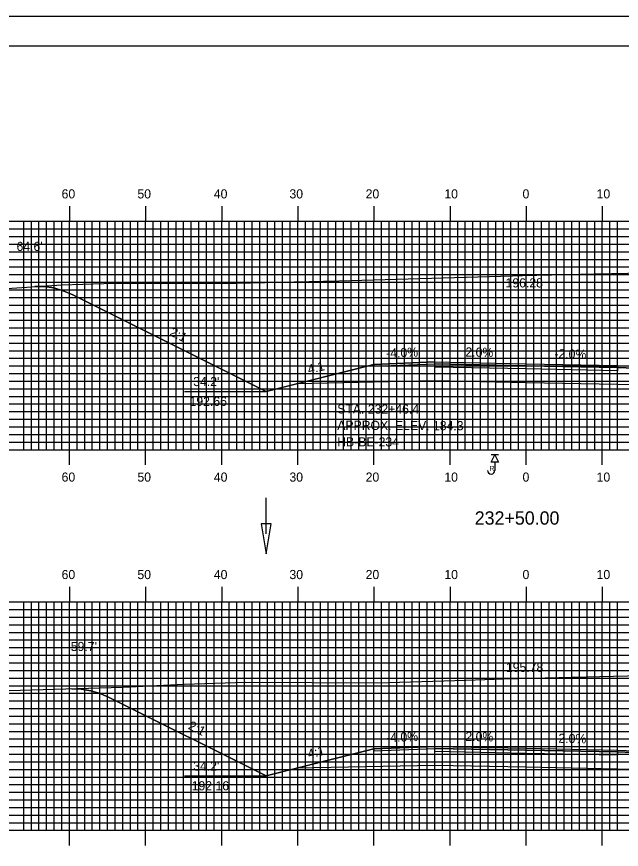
# Model space of a CAD drawing. Extents: x 1799568 to 1799912, y 442591 to 442811.
# Drawn here: x 1799667.1 to 1799746.5, y 442701.2 to 442810.5 of the extents above; entities that cross this region are included whole.
import ezdxf

# ---------------------------------------------------------------- set-up
doc = ezdxf.new("R2010")
doc.units = 0
for name, color, linetype in [('ANNOTATION', 7, 'Continuous'), ('BORDER', 7, 'Continuous'), ('BORING - REFUSAL', 7, 'Continuous'), ('D_Drainage_Ditch_Line', 7, 'Continuous'), ('D_Roadway_Centerline', 7, 'Continuous'), ('D_Roadway_Centerline_Text', 7, 'Continuous'), ('D_Roadway_Edge_Shoulder', 7, 'Continuous'), ('D_Roadway_Edge_TW', 7, 'Continuous'), ('D_Roadway_Pavement', 7, 'Continuous'), ('D_Roadway_SlopeLines', 7, 'Continuous'), ('D_Roadway_SubGrade', 7, 'Continuous'), ('D_Text_Standard', 7, 'Continuous'), ('H_V ANNOTATION', 7, 'Continuous'), ('MAJOR', 7, 'Continuous'), ('MINOR', 7, 'Continuous'), ('PDRAIN', 7, 'Continuous'), ('PLOT BOUNDARY', 7, 'Continuous'), ('S_Roadway_Centerline', 7, 'Continuous')]:
    doc.layers.add(name, color=color, linetype=linetype)

msp = doc.modelspace()

# ---------------------------------------------------------------- linework, layer by layer
at = {"layer": 'BORDER'}
msp.add_lwpolyline([(1799584.41, 442596.67), (1799904.41, 442596.67), (1799904.41, 442806.67), (1799584.41, 442806.67)], close=True, dxfattribs=at)
at = {"layer": 'BORING - REFUSAL'}
for p, q in [((1799730.39, 442752.97), (1799729.43, 442752.97)), ((1799729.91, 442752.01), (1799729.91, 442750.95))]:
    msp.add_line(p, q, dxfattribs=at)
msp.add_lwpolyline([(1799729.91, 442752.97), (1799730.39, 442752.01), (1799729.43, 442752.01)], close=True, dxfattribs=at)
msp.add_arc((1799729.42, 442750.95), 0.485, 180, 0, dxfattribs=at)
at = {"layer": 'D_Drainage_Ditch_Line'}
msp.add_line((1799699.84, 442742.63), (1799699.84, 442747.33), dxfattribs=at)
msp.add_lwpolyline([(1799700.49, 442743.94), (1799699.18, 442743.94), (1799699.84, 442740)], close=True, dxfattribs=at)
at = {"layer": 'D_Roadway_Centerline'}
for points in [[(1799669.45, 442775.1), (1799670.7, 442775.09), (1799671.95, 442774.91), (1799673.2, 442774.55), (1799674.45, 442774.02), (1799699.84, 442761.33), (1799703.84, 442762.33), (1799714.01, 442764.87), (1799722.01, 442765.19), (1799734.01, 442764.95), (1799746.01, 442764.71), (1799754.01, 442764.39), (1799764.18, 442761.85), (1799768.18, 442760.85), (1799798.21, 442775.86), (1799799.46, 442776.41), (1799800.71, 442776.8), (1799801.96, 442777.05), (1799803.21, 442777.14)], [(1799674.31, 442722.27), (1799675.56, 442722.22), (1799676.81, 442722.01), (1799678.06, 442721.63), (1799679.31, 442721.09), (1799699.84, 442710.83), (1799703.84, 442711.83), (1799714.01, 442714.37), (1799722.01, 442714.69), (1799734.01, 442714.45), (1799746.01, 442714.21), (1799754.01, 442713.89), (1799764.18, 442711.35), (1799768.18, 442710.35), (1799794.75, 442723.63), (1799796, 442724.18), (1799797.25, 442724.58), (1799798.5, 442724.84), (1799799.75, 442724.95)]]:
    msp.add_lwpolyline(points, dxfattribs=at)
at = {"layer": 'D_Roadway_Edge_Shoulder'}
for points in [[(1799722.01, 442765.19), (1799714.01, 442764.87), (1799714.01, 442764.62), (1799722.01, 442764.94)], [(1799746.01, 442764.71), (1799754.01, 442764.39), (1799754.01, 442764.14), (1799746.01, 442764.46)], [(1799722.01, 442714.69), (1799714.01, 442714.37), (1799714.01, 442714.12), (1799722.01, 442714.44)], [(1799746.01, 442714.21), (1799754.01, 442713.89), (1799754.01, 442713.64), (1799746.01, 442713.96)]]:
    msp.add_lwpolyline(points, close=True, dxfattribs=at)
at = {"layer": 'D_Roadway_Edge_TW'}
for points in [[(1799722.01, 442764.94), (1799722.01, 442765.19), (1799734.01, 442764.95), (1799746.01, 442764.71), (1799746.01, 442764.46), (1799734.01, 442764.7)], [(1799722.01, 442714.44), (1799722.01, 442714.69), (1799734.01, 442714.45), (1799746.01, 442714.21), (1799746.01, 442713.96), (1799734.01, 442714.2)]]:
    msp.add_lwpolyline(points, close=True, dxfattribs=at)
at = {"layer": 'D_Roadway_Pavement'}
for points in [[(1799722.01, 442764.52), (1799722.01, 442764.94), (1799734.01, 442764.7), (1799746.01, 442764.46), (1799746.01, 442764.04), (1799734.01, 442764.28)], [(1799722.01, 442714.02), (1799722.01, 442714.44), (1799734.01, 442714.2), (1799746.01, 442713.96), (1799746.01, 442713.54), (1799734.01, 442713.78)]]:
    msp.add_lwpolyline(points, close=True, dxfattribs=at)
at = {"layer": 'D_Roadway_SlopeLines'}
for points in [[(1799699.84, 442761.33), (1799674.45, 442774.02), (1799673.2, 442774.55), (1799671.95, 442774.91), (1799670.7, 442775.09), (1799669.45, 442775.1)], [(1799714.01, 442764.87), (1799699.84, 442761.33)], [(1799699.84, 442710.83), (1799679.31, 442721.09), (1799678.06, 442721.63), (1799676.81, 442722.01), (1799675.56, 442722.22), (1799674.31, 442722.27)], [(1799714.01, 442714.37), (1799699.84, 442710.83)]]:
    msp.add_lwpolyline(points, dxfattribs=at)
at = {"layer": 'D_Roadway_SubGrade'}
for points in [[(1799722.01, 442762.69), (1799703.84, 442762.33), (1799714.01, 442764.87), (1799714.01, 442764.62), (1799722.01, 442764.94), (1799734.01, 442764.7), (1799746.01, 442764.46), (1799754.01, 442764.14), (1799754.01, 442764.39), (1799764.18, 442761.85), (1799746.01, 442762.21), (1799734.01, 442762.45)], [(1799722.01, 442712.19), (1799703.84, 442711.83), (1799714.01, 442714.37), (1799714.01, 442714.12), (1799722.01, 442714.44), (1799734.01, 442714.2), (1799746.01, 442713.96), (1799754.01, 442713.64), (1799754.01, 442713.89), (1799764.18, 442711.35), (1799746.01, 442711.71), (1799734.01, 442711.95)]]:
    msp.add_lwpolyline(points, close=True, dxfattribs=at)
at = {"layer": 'MAJOR'}
for p, q in [((1799674.01, 442785.67), (1799674.01, 442783.67)), ((1799684.01, 442785.67), (1799684.01, 442783.67)), ((1799694.01, 442785.67), (1799694.01, 442783.67)), ((1799704.01, 442785.67), (1799704.01, 442783.67)), ((1799714.01, 442785.67), (1799714.01, 442783.67)), ((1799724.01, 442785.67), (1799724.01, 442783.67)), ((1799734.01, 442785.67), (1799734.01, 442783.67)), ((1799744.01, 442785.67), (1799744.01, 442783.67)), ((1799594.01, 442783.67), (1799874.01, 442783.67)), ((1799594.01, 442783.67), (1799874.01, 442783.67)), ((1799674.01, 442753.67), (1799674.01, 442783.67)), ((1799684.01, 442753.67), (1799684.01, 442783.67)), ((1799694.01, 442753.67), (1799694.01, 442783.67)), ((1799704.01, 442753.67), (1799704.01, 442783.67)), ((1799714.01, 442753.67), (1799714.01, 442783.67)), ((1799724.01, 442753.67), (1799724.01, 442783.67)), ((1799734.01, 442753.67), (1799734.01, 442783.67)), ((1799744.01, 442753.67), (1799744.01, 442783.67)), ((1799594.01, 442778.67), (1799874.01, 442778.67)), ((1799594.01, 442773.67), (1799874.01, 442773.67)), ((1799594.01, 442768.67), (1799874.01, 442768.67)), ((1799594.01, 442763.67), (1799874.01, 442763.67)), ((1799594.01, 442758.67), (1799874.01, 442758.67)), ((1799594.01, 442753.67), (1799874.01, 442753.67)), ((1799594.01, 442753.67), (1799874.01, 442753.67)), ((1799674.01, 442751.66), (1799674.01, 442753.67)), ((1799684.01, 442751.66), (1799684.01, 442753.67)), ((1799694.01, 442751.66), (1799694.01, 442753.67)), ((1799704.01, 442751.66), (1799704.01, 442753.67)), ((1799714.01, 442751.66), (1799714.01, 442753.67)), ((1799724.01, 442751.66), (1799724.01, 442753.67)), ((1799734.01, 442751.66), (1799734.01, 442753.67)), ((1799744.01, 442751.66), (1799744.01, 442753.67)), ((1799674.01, 442735.67), (1799674.01, 442733.67)), ((1799684.01, 442735.67), (1799684.01, 442733.67)), ((1799694.01, 442735.67), (1799694.01, 442733.67)), ((1799704.01, 442735.67), (1799704.01, 442733.67)), ((1799714.01, 442735.67), (1799714.01, 442733.67)), ((1799724.01, 442735.67), (1799724.01, 442733.67)), ((1799734.01, 442735.67), (1799734.01, 442733.67)), ((1799744.01, 442735.67), (1799744.01, 442733.67)), ((1799594.01, 442733.67), (1799874.01, 442733.67)), ((1799594.01, 442733.67), (1799874.01, 442733.67)), ((1799674.01, 442703.67), (1799674.01, 442733.67)), ((1799684.01, 442703.67), (1799684.01, 442733.67)), ((1799694.01, 442703.67), (1799694.01, 442733.67)), ((1799704.01, 442703.67), (1799704.01, 442733.67)), ((1799714.01, 442703.67), (1799714.01, 442733.67)), ((1799724.01, 442703.67), (1799724.01, 442733.67)), ((1799734.01, 442703.67), (1799734.01, 442733.67)), ((1799744.01, 442703.67), (1799744.01, 442733.67)), ((1799594.01, 442728.67), (1799874.01, 442728.67)), ((1799594.01, 442723.67), (1799874.01, 442723.67)), ((1799594.01, 442718.67), (1799874.01, 442718.67)), ((1799594.01, 442713.67), (1799874.01, 442713.67)), ((1799594.01, 442708.67), (1799874.01, 442708.67)), ((1799594.01, 442703.67), (1799874.01, 442703.67)), ((1799594.01, 442703.67), (1799874.01, 442703.67)), ((1799674.01, 442701.66), (1799674.01, 442703.67)), ((1799684.01, 442701.66), (1799684.01, 442703.67)), ((1799694.01, 442701.66), (1799694.01, 442703.67)), ((1799704.01, 442701.66), (1799704.01, 442703.67)), ((1799714.01, 442701.66), (1799714.01, 442703.67)), ((1799724.01, 442701.66), (1799724.01, 442703.67)), ((1799734.01, 442701.66), (1799734.01, 442703.67)), ((1799744.01, 442701.66), (1799744.01, 442703.67))]:
    msp.add_line(p, q, dxfattribs=at)
at = {"layer": 'MINOR'}
for p, q in [((1799668.01, 442753.67), (1799668.01, 442783.67)), ((1799669.01, 442753.67), (1799669.01, 442783.67)), ((1799670.01, 442753.67), (1799670.01, 442783.67)), ((1799671.01, 442753.67), (1799671.01, 442783.67)), ((1799672.01, 442753.67), (1799672.01, 442783.67)), ((1799673.01, 442753.67), (1799673.01, 442783.67)), ((1799675.01, 442753.67), (1799675.01, 442783.67)), ((1799676.01, 442753.67), (1799676.01, 442783.67)), ((1799677.01, 442753.67), (1799677.01, 442783.67)), ((1799678.01, 442753.67), (1799678.01, 442783.67)), ((1799679.01, 442753.67), (1799679.01, 442783.67)), ((1799680.01, 442753.67), (1799680.01, 442783.67)), ((1799681.01, 442753.67), (1799681.01, 442783.67)), ((1799682.01, 442753.67), (1799682.01, 442783.67)), ((1799683.01, 442753.67), (1799683.01, 442783.67)), ((1799685.01, 442753.67), (1799685.01, 442783.67)), ((1799686.01, 442753.67), (1799686.01, 442783.67)), ((1799687.01, 442753.67), (1799687.01, 442783.67)), ((1799688.01, 442753.67), (1799688.01, 442783.67)), ((1799689.01, 442753.67), (1799689.01, 442783.67)), ((1799690.01, 442753.67), (1799690.01, 442783.67)), ((1799691.01, 442753.67), (1799691.01, 442783.67)), ((1799692.01, 442753.67), (1799692.01, 442783.67)), ((1799693.01, 442753.67), (1799693.01, 442783.67)), ((1799695.01, 442753.67), (1799695.01, 442783.67)), ((1799696.01, 442753.67), (1799696.01, 442783.67)), ((1799697.01, 442753.67), (1799697.01, 442783.67)), ((1799698.01, 442753.67), (1799698.01, 442783.67)), ((1799699.01, 442753.67), (1799699.01, 442783.67)), ((1799700.01, 442753.67), (1799700.01, 442783.67)), ((1799701.01, 442753.67), (1799701.01, 442783.67)), ((1799702.01, 442753.67), (1799702.01, 442783.67)), ((1799703.01, 442753.67), (1799703.01, 442783.67)), ((1799705.01, 442753.67), (1799705.01, 442783.67)), ((1799706.01, 442753.67), (1799706.01, 442783.67)), ((1799707.01, 442753.67), (1799707.01, 442783.67)), ((1799708.01, 442753.67), (1799708.01, 442783.67)), ((1799709.01, 442753.67), (1799709.01, 442783.67)), ((1799710.01, 442753.67), (1799710.01, 442783.67)), ((1799711.01, 442753.67), (1799711.01, 442783.67)), ((1799712.01, 442753.67), (1799712.01, 442783.67)), ((1799713.01, 442753.67), (1799713.01, 442783.67)), ((1799715.01, 442753.67), (1799715.01, 442783.67)), ((1799716.01, 442753.67), (1799716.01, 442783.67)), ((1799717.01, 442753.67), (1799717.01, 442783.67)), ((1799718.01, 442753.67), (1799718.01, 442783.67)), ((1799719.01, 442753.67), (1799719.01, 442783.67)), ((1799720.01, 442753.67), (1799720.01, 442783.67)), ((1799721.01, 442753.67), (1799721.01, 442783.67)), ((1799722.01, 442753.67), (1799722.01, 442783.67)), ((1799723.01, 442753.67), (1799723.01, 442783.67)), ((1799725.01, 442753.67), (1799725.01, 442783.67)), ((1799726.01, 442753.67), (1799726.01, 442783.67)), ((1799727.01, 442753.67), (1799727.01, 442783.67)), ((1799728.01, 442753.67), (1799728.01, 442783.67)), ((1799729.01, 442753.67), (1799729.01, 442783.67)), ((1799730.01, 442753.67), (1799730.01, 442783.67)), ((1799731.01, 442753.67), (1799731.01, 442783.67)), ((1799732.01, 442753.67), (1799732.01, 442783.67)), ((1799733.01, 442753.67), (1799733.01, 442783.67)), ((1799735.01, 442753.67), (1799735.01, 442783.67)), ((1799736.01, 442753.67), (1799736.01, 442783.67)), ((1799737.01, 442753.67), (1799737.01, 442783.67)), ((1799738.01, 442753.67), (1799738.01, 442783.67)), ((1799739.01, 442753.67), (1799739.01, 442783.67)), ((1799740.01, 442753.67), (1799740.01, 442783.67)), ((1799741.01, 442753.67), (1799741.01, 442783.67)), ((1799742.01, 442753.67), (1799742.01, 442783.67)), ((1799743.01, 442753.67), (1799743.01, 442783.67)), ((1799745.01, 442753.67), (1799745.01, 442783.67)), ((1799746.01, 442753.67), (1799746.01, 442783.67)), ((1799594.01, 442782.67), (1799874.01, 442782.67)), ((1799594.01, 442781.67), (1799874.01, 442781.67)), ((1799594.01, 442780.67), (1799874.01, 442780.67)), ((1799594.01, 442779.67), (1799874.01, 442779.67)), ((1799594.01, 442777.67), (1799874.01, 442777.67)), ((1799594.01, 442776.67), (1799874.01, 442776.67)), ((1799594.01, 442775.67), (1799874.01, 442775.67)), ((1799594.01, 442774.67), (1799874.01, 442774.67)), ((1799594.01, 442772.67), (1799874.01, 442772.67)), ((1799594.01, 442771.67), (1799874.01, 442771.67)), ((1799594.01, 442770.67), (1799874.01, 442770.67)), ((1799594.01, 442769.67), (1799874.01, 442769.67)), ((1799594.01, 442767.67), (1799874.01, 442767.67)), ((1799594.01, 442766.67), (1799874.01, 442766.67)), ((1799594.01, 442765.67), (1799874.01, 442765.67)), ((1799594.01, 442764.67), (1799874.01, 442764.67)), ((1799594.01, 442762.67), (1799874.01, 442762.67)), ((1799594.01, 442761.67), (1799874.01, 442761.67)), ((1799594.01, 442760.67), (1799874.01, 442760.67)), ((1799594.01, 442759.67), (1799874.01, 442759.67)), ((1799594.01, 442757.67), (1799874.01, 442757.67)), ((1799594.01, 442756.67), (1799874.01, 442756.67)), ((1799594.01, 442755.67), (1799874.01, 442755.67)), ((1799594.01, 442754.67), (1799874.01, 442754.67)), ((1799668.01, 442703.67), (1799668.01, 442733.67)), ((1799669.01, 442703.67), (1799669.01, 442733.67)), ((1799670.01, 442703.67), (1799670.01, 442733.67)), ((1799671.01, 442703.67), (1799671.01, 442733.67)), ((1799672.01, 442703.67), (1799672.01, 442733.67)), ((1799673.01, 442703.67), (1799673.01, 442733.67)), ((1799675.01, 442703.67), (1799675.01, 442733.67)), ((1799676.01, 442703.67), (1799676.01, 442733.67)), ((1799677.01, 442703.67), (1799677.01, 442733.67)), ((1799678.01, 442703.67), (1799678.01, 442733.67)), ((1799679.01, 442703.67), (1799679.01, 442733.67)), ((1799680.01, 442703.67), (1799680.01, 442733.67)), ((1799681.01, 442703.67), (1799681.01, 442733.67)), ((1799682.01, 442703.67), (1799682.01, 442733.67)), ((1799683.01, 442703.67), (1799683.01, 442733.67)), ((1799685.01, 442703.67), (1799685.01, 442733.67)), ((1799686.01, 442703.67), (1799686.01, 442733.67)), ((1799687.01, 442703.67), (1799687.01, 442733.67)), ((1799688.01, 442703.67), (1799688.01, 442733.67)), ((1799689.01, 442703.67), (1799689.01, 442733.67)), ((1799690.01, 442703.67), (1799690.01, 442733.67)), ((1799691.01, 442703.67), (1799691.01, 442733.67)), ((1799692.01, 442703.67), (1799692.01, 442733.67)), ((1799693.01, 442703.67), (1799693.01, 442733.67)), ((1799695.01, 442703.67), (1799695.01, 442733.67)), ((1799696.01, 442703.67), (1799696.01, 442733.67)), ((1799697.01, 442703.67), (1799697.01, 442733.67)), ((1799698.01, 442703.67), (1799698.01, 442733.67)), ((1799699.01, 442703.67), (1799699.01, 442733.67)), ((1799700.01, 442703.67), (1799700.01, 442733.67)), ((1799701.01, 442703.67), (1799701.01, 442733.67)), ((1799702.01, 442703.67), (1799702.01, 442733.67)), ((1799703.01, 442703.67), (1799703.01, 442733.67)), ((1799705.01, 442703.67), (1799705.01, 442733.67)), ((1799706.01, 442703.67), (1799706.01, 442733.67)), ((1799707.01, 442703.67), (1799707.01, 442733.67)), ((1799708.01, 442703.67), (1799708.01, 442733.67)), ((1799709.01, 442703.67), (1799709.01, 442733.67)), ((1799710.01, 442703.67), (1799710.01, 442733.67)), ((1799711.01, 442703.67), (1799711.01, 442733.67)), ((1799712.01, 442703.67), (1799712.01, 442733.67)), ((1799713.01, 442703.67), (1799713.01, 442733.67)), ((1799715.01, 442703.67), (1799715.01, 442733.67)), ((1799716.01, 442703.67), (1799716.01, 442733.67)), ((1799717.01, 442703.67), (1799717.01, 442733.67)), ((1799718.01, 442703.67), (1799718.01, 442733.67)), ((1799719.01, 442703.67), (1799719.01, 442733.67)), ((1799720.01, 442703.67), (1799720.01, 442733.67)), ((1799721.01, 442703.67), (1799721.01, 442733.67)), ((1799722.01, 442703.67), (1799722.01, 442733.67)), ((1799723.01, 442703.67), (1799723.01, 442733.67)), ((1799725.01, 442703.67), (1799725.01, 442733.67)), ((1799726.01, 442703.67), (1799726.01, 442733.67)), ((1799727.01, 442703.67), (1799727.01, 442733.67)), ((1799728.01, 442703.67), (1799728.01, 442733.67)), ((1799729.01, 442703.67), (1799729.01, 442733.67)), ((1799730.01, 442703.67), (1799730.01, 442733.67)), ((1799731.01, 442703.67), (1799731.01, 442733.67)), ((1799732.01, 442703.67), (1799732.01, 442733.67)), ((1799733.01, 442703.67), (1799733.01, 442733.67)), ((1799735.01, 442703.67), (1799735.01, 442733.67)), ((1799736.01, 442703.67), (1799736.01, 442733.67)), ((1799737.01, 442703.67), (1799737.01, 442733.67)), ((1799738.01, 442703.67), (1799738.01, 442733.67)), ((1799739.01, 442703.67), (1799739.01, 442733.67)), ((1799740.01, 442703.67), (1799740.01, 442733.67)), ((1799741.01, 442703.67), (1799741.01, 442733.67)), ((1799742.01, 442703.67), (1799742.01, 442733.67)), ((1799743.01, 442703.67), (1799743.01, 442733.67)), ((1799745.01, 442703.67), (1799745.01, 442733.67)), ((1799746.01, 442703.67), (1799746.01, 442733.67)), ((1799594.01, 442732.67), (1799874.01, 442732.67)), ((1799594.01, 442731.67), (1799874.01, 442731.67)), ((1799594.01, 442730.67), (1799874.01, 442730.67)), ((1799594.01, 442729.67), (1799874.01, 442729.67)), ((1799594.01, 442727.67), (1799874.01, 442727.67)), ((1799594.01, 442726.67), (1799874.01, 442726.67)), ((1799594.01, 442725.67), (1799874.01, 442725.67)), ((1799594.01, 442724.67), (1799874.01, 442724.67)), ((1799594.01, 442722.67), (1799874.01, 442722.67)), ((1799594.01, 442721.67), (1799874.01, 442721.67)), ((1799594.01, 442720.67), (1799874.01, 442720.67)), ((1799594.01, 442719.67), (1799874.01, 442719.67)), ((1799594.01, 442717.67), (1799874.01, 442717.67)), ((1799594.01, 442716.67), (1799874.01, 442716.67)), ((1799594.01, 442715.67), (1799874.01, 442715.67)), ((1799594.01, 442714.67), (1799874.01, 442714.67)), ((1799594.01, 442712.67), (1799874.01, 442712.67)), ((1799594.01, 442711.67), (1799874.01, 442711.67)), ((1799594.01, 442710.67), (1799874.01, 442710.67)), ((1799594.01, 442709.67), (1799874.01, 442709.67)), ((1799594.01, 442707.67), (1799874.01, 442707.67)), ((1799594.01, 442706.67), (1799874.01, 442706.67)), ((1799594.01, 442705.67), (1799874.01, 442705.67)), ((1799594.01, 442704.67), (1799874.01, 442704.67))]:
    msp.add_line(p, q, dxfattribs=at)
at = {"layer": 'PDRAIN'}
for p, q in [((1799689.11, 442761.33), (1799699.84, 442761.33)), ((1799689.11, 442710.83), (1799699.84, 442710.83))]:
    msp.add_line(p, q, dxfattribs=at)
at = {"layer": 'PLOT BOUNDARY'}
msp.add_lwpolyline([(1799568.22, 442590.55), (1799908.22, 442590.55), (1799908.22, 442810.55), (1799568.22, 442810.55)], close=True, dxfattribs=at)
at = {"layer": 'S_Roadway_Centerline'}
for points in [[(1799594.01, 442772.87), (1799612.88, 442772.89), (1799616.92, 442772.95), (1799637.36, 442774.28), (1799638.29, 442774.36), (1799639.12, 442774.38), (1799660.98, 442774.53), (1799661.78, 442774.57), (1799673.01, 442775.34), (1799678.53, 442775.5), (1799695.85, 442775.53), (1799707.37, 442775.82), (1799709.4, 442775.86), (1799732.2, 442776.5), (1799733.54, 442776.55), (1799743.03, 442776.75), (1799756.05, 442777.02), (1799765.34, 442777.04), (1799776.04, 442777.28), (1799778.11, 442777.28), (1799780.07, 442777.19), (1799788.87, 442776.77), (1799799.24, 442777.09)], [(1799594.01, 442719.89), (1799595.64, 442719.95), (1799613.16, 442720.63), (1799618.33, 442720.65), (1799635.69, 442721.39), (1799641.86, 442721.73), (1799650.01, 442721.67), (1799659.41, 442721.95), (1799662.94, 442722.07), (1799666.11, 442722.03), (1799681, 442722.46), (1799689.09, 442722.87), (1799697.17, 442723.13), (1799714.49, 442723.04), (1799726.1, 442723.39), (1799731.09, 442723.58), (1799750.91, 442724.04), (1799755.54, 442724.14), (1799760.22, 442724.12), (1799773.17, 442724.3), (1799784.95, 442724.59), (1799790.22, 442724.67), (1799809.27, 442725.24)]]:
    msp.add_lwpolyline(points, dxfattribs=at)

# ---------------------------------------------------------------- texts
at = {"layer": 'ANNOTATION'}
for s, rotation, p in [('2:1', 333.4349, (1799687.08, 442768.74)), ('-4.0%', 2.2906, (1799715.64, 442765.74)), ('2.0%', 358.8542, (1799726.02, 442765.91)), ('-2.0%', 358.8542, (1799737.7, 442765.68)), ('4:1', 14.0362, (1799705.46, 442763.59)), ('2:1', 333.4349, (1799689.51, 442717.03)), ('-4.0%', 2.2906, (1799715.64, 442715.24)), ('2.0%', 358.8542, (1799726.02, 442715.41)), ('-2.0%', 358.8542, (1799737.7, 442715.18)), ('4:1', 14.0362, (1799705.46, 442713.09))]:
    msp.add_text(s, height=1.2, rotation=rotation, dxfattribs=at).set_placement(p)
for s, p in [("34.2'", (1799690.27, 442762.02)), ('192.66', (1799689.79, 442759.42)), ("34.2'", (1799690.27, 442711.52)), ('192.16', (1799690.07, 442708.92))]:
    msp.add_text(s, height=1.2, dxfattribs=at).set_placement(p)
at = {"layer": 'BORING - REFUSAL'}
for s, p in [('STA. 232+46.4', (1799709.19, 442758.43)), ('APPROX. ELEV. 184.3', (1799709.19, 442756.27)), ('HB-BE-234', (1799709.18, 442754.11))]:
    msp.add_text(s, height=1.2, rotation=359.8142, dxfattribs=at).set_placement(p)
msp.add_text('R', height=0.64, dxfattribs=at).set_placement((1799729.2, 442750.89))
at = {"layer": 'D_Roadway_Centerline'}
for s, p in [('C', (1799734, 442764.95)), ('L', (1799734.01, 442764.94)), ('C', (1799734, 442714.45)), ('L', (1799734.01, 442714.44))]:
    msp.add_text(s, height=0.0146, dxfattribs=at).set_placement(p)
at = {"layer": 'D_Roadway_Centerline_Text'}
for s, p in [('196.28', (1799731.3, 442774.98)), ('195.78', (1799731.35, 442724.48))]:
    msp.add_text(s, height=1.2, dxfattribs=at).set_placement(p)
at = {"layer": 'D_Text_Standard'}
for s, p in [("64.6'", (1799667.06, 442779.77)), ("59.7'", (1799674.19, 442727.22))]:
    msp.add_text(s, height=1.2, dxfattribs=at).set_placement(p)
at = {"layer": 'H_V ANNOTATION'}
for s, height, p in [('60', 1.2, (1799672.98, 442786.67)), ('50', 1.2, (1799682.94, 442786.67)), ('40', 1.2, (1799692.98, 442786.67)), ('30', 1.2, (1799702.91, 442786.67)), ('20', 1.2, (1799712.92, 442786.67)), ('10', 1.2, (1799723.26, 442786.67)), ('0', 1.2, (1799733.53, 442786.67)), ('10', 1.2, (1799743.26, 442786.67)), ('60', 1.2, (1799672.98, 442749.47)), ('50', 1.2, (1799682.94, 442749.47)), ('40', 1.2, (1799692.98, 442749.47)), ('30', 1.2, (1799702.91, 442749.47)), ('20', 1.2, (1799712.92, 442749.47)), ('10', 1.2, (1799723.26, 442749.47)), ('0', 1.2, (1799733.53, 442749.47)), ('10', 1.2, (1799743.26, 442749.47)), ('232+50.00', 1.75, (1799727.25, 442743.82)), ('60', 1.2, (1799672.98, 442736.67)), ('50', 1.2, (1799682.94, 442736.67)), ('40', 1.2, (1799692.98, 442736.67)), ('30', 1.2, (1799702.91, 442736.67)), ('20', 1.2, (1799712.92, 442736.67)), ('10', 1.2, (1799723.26, 442736.67)), ('0', 1.2, (1799733.53, 442736.67)), ('10', 1.2, (1799743.26, 442736.67))]:
    msp.add_text(s, height=height, dxfattribs=at).set_placement(p)

doc.saveas('drawing.dxf')
